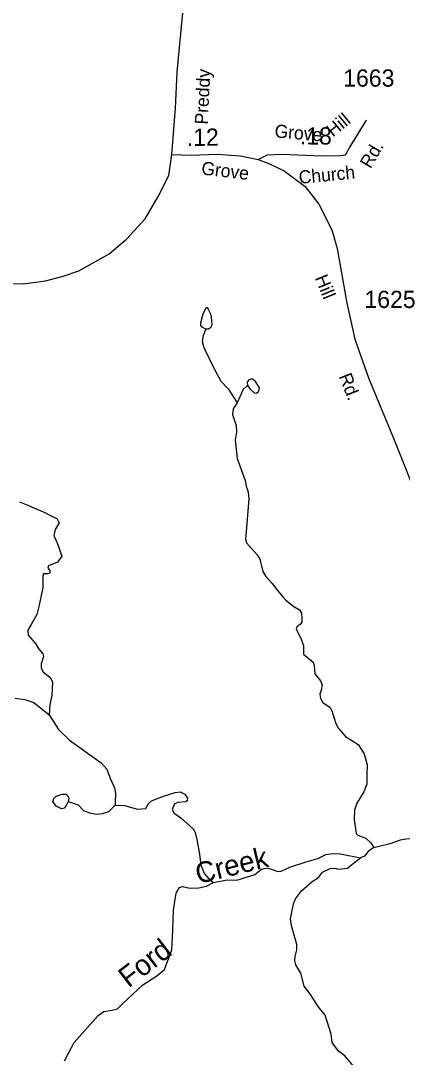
# Model space of a CAD drawing. Extents: x 2056842 to 2160602, y 826753 to 1016856.
# Drawn here: x 2135919 to 2138687, y 873341 to 880850 of the extents above; entities that cross this region are included whole.
import ezdxf

# ---------------------------------------------------------------- set-up
doc = ezdxf.new("R2010")
doc.units = 0
for name, color, linetype in [('Exist Hydrographic Creek Single Shore', 7, 'Continuous'), ('Exist Hydrographic Creek Single Shore Label', 7, 'Continuous'), ('Exist Hydrographic Misc Water Feature', 7, 'Continuous'), ('Exist Road Secondary Mileage Hundredths English Label', 7, 'Continuous'), ('Exist Road Secondary Type 20 Attributed', 7, 'Continuous'), ('Exist Road Secondary Type 41 Attributed', 7, 'Continuous'), ('Exist Road Secondary Type 51 Attributed', 7, 'Continuous'), ('Exist Road Secondary Type 51 Label', 7, 'Continuous'), ('Exist Road Secondary Type 51 Number Label', 7, 'Continuous')]:
    doc.layers.add(name, color=color, linetype=linetype)

msp = doc.modelspace()

# ---------------------------------------------------------------- linework, layer by layer
at = {"layer": 'Exist Hydrographic Creek Single Shore'}
for points in [[(2137487.9, 878081.8), (2137460, 878037.6), (2137454.3, 877997.6), (2137482.1, 877918.2), (2137483.3, 877868), (2137474.5, 877811.4), (2137490, 877677.9), (2137547.4, 877519.9), (2137554.9, 877478.5), (2137562.4, 877458.4), (2137570, 877433.3), (2137573.7, 877384.3), (2137567.5, 877300.1), (2137559.9, 877204.3), (2137548.4, 877094.2), (2137556.4, 877068.3), (2137635, 876980.7), (2137652.8, 876948.7), (2137675.4, 876860.8), (2137697.3, 876822.9), (2137742, 876773.1), (2137780.9, 876721.6), (2137819.9, 876675.1), (2137842.1, 876651.6), (2137900.2, 876607.3), (2137941.7, 876580.9), (2137955.5, 876557), (2137959.2, 876518.1)], [(2136186.7, 877060.3), (2136217.2, 876970.3), (2136185.4, 876928.2), (2136119.4, 876900), (2136115.7, 876883.9), (2136129.7, 876868), (2136129.7, 876848), (2136113.7, 876843.9), (2136084.5, 876843), (2136078.2, 876825.4), (2136078.2, 876743.8), (2136051.9, 876616.9), (2136036.8, 876547.8), (2135995.4, 876476.1), (2135971.5, 876435.9), (2135972.8, 876399), (2136024.2, 876339.9), (2136051.9, 876293.5), (2136079.5, 876263.3), (2136083.3, 876244.5), (2136068.2, 876191.7), (2136066.9, 876159), (2136082, 876132.6), (2136133.5, 876091.2), (2136148.6, 876059.8), (2136143.5, 875961.5), (2136131, 875897.4), (2136126.2, 875820.2)], [(2137959.2, 876518.1), (2137958, 876493), (2137945.4, 876476.6), (2137924.1, 876461.6), (2137916.5, 876445.2), (2137954.2, 876368.6), (2137970.5, 876322.1), (2137969.8, 876280.2), (2137969.8, 876260.2), (2138040.1, 876202.5), (2138048.1, 876178.6), (2138052.4, 876118.7), (2138094.9, 876067), (2138104.9, 876038.2), (2138097.4, 876000.5), (2138089.8, 875971.6), (2138094.9, 875942.7), (2138111.3, 875910.9), (2138163.9, 875873.6), (2138175.2, 875849.7), (2138204.1, 875758), (2138225.4, 875721.5), (2138274.4, 875665), (2138366.1, 875607.2), (2138411.3, 875539.4), (2138431.4, 875459.5), (2138428.9, 875394.1), (2138430.1, 875318.7), (2138408.2, 875264.3), (2138356.5, 875182.2), (2138340.9, 875130.1), (2138339.1, 875062.1), (2138351.4, 874962.2), (2138363.7, 874950.2), (2138423.6, 874928.4), (2138459, 874893.3), (2138481.6, 874859.4)], [(2135877.7, 875941.1), (2135949.6, 875931.4), (2136013.8, 875911.7), (2136126.2, 875820.2)], [(2136126.2, 875820.2), (2136192.6, 875714.5), (2136272.9, 875637.6), (2136501.4, 875474.3), (2136544.1, 875427.8), (2136565.4, 875367.5), (2136599.3, 875292.1), (2136605.6, 875251.9), (2136602.9, 875186.4), (2136602.9, 875166.4)], [(2136602.9, 875166.4), (2136670.8, 875164.8), (2136765.1, 875139.1), (2136826.8, 875143.4), (2136846.9, 875179.5), (2136866.6, 875199.5), (2136910.8, 875215.5), (2136954.6, 875231.9), (2137040.3, 875258.4), (2137076.4, 875262.5), (2137110.4, 875246.7), (2137128.7, 875218.8), (2137126.6, 875198.8), (2137114.7, 875190.7), (2137059, 875186.5), (2137035, 875176.3), (2137016.9, 875136.3), (2137031.1, 875108.4), (2137081.1, 875074.5), (2137169.7, 874995), (2137184.5, 874969), (2137197, 874917.4), (2137216.4, 874813.2), (2137226.7, 874733.2), (2137252.9, 874669.3), (2137283.1, 874633.5), (2137317.6, 874605.9)], [(2138481.6, 874859.4), (2138519.3, 874869.4), (2138598.4, 874889.5), (2138673.7, 874914.7), (2138713.9, 874922.2), (2138781.7, 874927.2), (2138838.2, 874915.9), (2138885.9, 874895.8), (2138938.7, 874865.7), (2138978.8, 874861.9), (2139011.5, 874868.2), (2139124.5, 874919.7), (2139176, 874934.8), (2139199.8, 874948.6), (2139221.2, 874949.9), (2139235, 874937.3), (2139266.4, 874892.1), (2139285.2, 874866.9), (2139527.6, 874828), (2139552.7, 874835.5), (2139586.6, 874885.8), (2139609.2, 874897.1)], [(2137317.6, 874605.9), (2137416.8, 874626), (2137487.1, 874624.7), (2137617.7, 874663.6), (2137666.7, 874702.6), (2137694.3, 874710.1), (2137724.7, 874707.2), (2137784.6, 874685.6), (2137808.6, 874687.8), (2137871.3, 874718.9), (2137990.6, 874756.6), (2138074.8, 874781.5), (2138132, 874809), (2138186, 874817.4), (2138236.1, 874813.4), (2138383.7, 874786.5)], [(2138481.6, 874859.4), (2138438.9, 874830.5), (2138412.5, 874796.6), (2138383.7, 874786.5)], [(2138350.8, 873256.5), (2138270.6, 873350.1), (2138224.5, 873385.9), (2138178.1, 873447.7), (2138171.8, 873507.6), (2138127.3, 873645.4), (2138077, 873709.2), (2138020.7, 873794.9), (2137976.4, 873854.8), (2137950.1, 873950.5), (2137913.6, 874010.4), (2137907.7, 874038.4), (2137909.3, 874070.4), (2137921.4, 874118.5), (2137921.2, 874158.5), (2137882.7, 874292.3), (2137876.3, 874344.2), (2137897.8, 874452.3), (2137911.6, 874488.3), (2137955.5, 874546.5), (2138033.2, 874614.8), (2138078.9, 874643), (2138108.8, 874681.1), (2138164.6, 874709.4), (2138196.6, 874709.5), (2138224.7, 874703.7), (2138288.7, 874709.9), (2138307.1, 874726.2), (2138342.4, 874754.1), (2138383.7, 874786.5)], [(2136235.2, 873315.3), (2136265.3, 873369.3), (2136306.5, 873447.2), (2136480.1, 873643.5), (2136521.5, 873672.4), (2136583, 873682.4), (2136620.7, 873692.5), (2136659.6, 873730.2), (2136804, 873864.6), (2136907, 873931.2), (2136962.2, 873977.7), (2137015, 874118.4), (2137022.5, 874264.1), (2137026.3, 874409.9), (2137046.4, 874529.2), (2137071.5, 874570.7), (2137091.6, 874578.2), (2137145.6, 874565.7), (2137212.1, 874568.2), (2137267.4, 874579.5), (2137317.6, 874605.9)]]:
    msp.add_lwpolyline(points, dxfattribs=at)
at = {"layer": 'Exist Hydrographic Misc Water Feature'}
for points in [[(2137261.1, 878616), (2137234.7, 878628.6), (2137224.7, 878642.4), (2137225.9, 878661.3), (2137243.5, 878726.6), (2137263.6, 878771.8), (2137272.4, 878773.1), (2137278.7, 878759.3), (2137295, 878726.6), (2137300, 878704), (2137305, 878646.2), (2137298.8, 878627.3), (2137281.2, 878614.8), (2137261.1, 878616)], [(2137261.1, 878616), (2137242.2, 878568.3), (2137236, 878529.3), (2137247.3, 878482.9), (2137316.3, 878338.4), (2137370.3, 878237.6), (2137423.5, 878183.4), (2137487.9, 878081.8)], [(2137565, 878206.2), (2137583.8, 878181.3), (2137611.4, 878153.7), (2137629, 878152.4), (2137646.6, 878165), (2137650.3, 878191.4), (2137621.5, 878236.6), (2137596.3, 878255.4), (2137573.7, 878249.2), (2137562.4, 878230.3), (2137565, 878206.2)], [(2137565, 878206.2), (2137531.6, 878177.9), (2137487.9, 878081.8)], [(2135909.4, 877365), (2135971.5, 877340.5), (2136019.6, 877319.4), (2136093.3, 877287), (2136126, 877270.7), (2136182, 877242.2), (2136198.2, 877212.3), (2136168.4, 877164.1), (2136158.4, 877120.1), (2136186.7, 877060.3)], [(2136262.8, 875194.1), (2136249, 875163.9), (2136233.9, 875146.4), (2136213.9, 875141.3), (2136174.9, 875160.2), (2136152.3, 875194.1), (2136158.6, 875215.5), (2136174.9, 875233.1), (2136218.9, 875246.9), (2136247.8, 875246.9), (2136260.3, 875235.6), (2136266.6, 875214.2), (2136262.8, 875194.1)], [(2136262.8, 875194.1), (2136334.9, 875169.3), (2136375.1, 875129.4), (2136425.1, 875109.7), (2136473.3, 875101.9), (2136513.1, 875106), (2136557.2, 875122.2), (2136602.9, 875166.4)]]:
    msp.add_lwpolyline(points, dxfattribs=at)
at = {"layer": 'Exist Road Secondary Type 20 Attributed'}
msp.add_lwpolyline([(2137014, 879881.6), (2137041.7, 880215.4), (2137053.1, 880477.8), (2137093.9, 880906.6), (2137109.1, 880999.7), (2137169.9, 881267.8), (2137208.9, 881439.9), (2137218.4, 881550.2), (2137248.8, 881991.4), (2137283.9, 882418.2), (2137285.8, 882469.6), (2137245.9, 882602.7)], dxfattribs=at)
at = {"layer": 'Exist Road Secondary Type 41 Attributed'}
msp.add_lwpolyline([(2137642.1, 879845.3), (2137708.6, 879878.8), (2137809.3, 879882.6), (2138105.8, 879871.2), (2138242, 879872.4), (2138276.1, 879878.4), (2138303.2, 879929.6), (2138427.5, 880128.2)], dxfattribs=at)
at = {"layer": 'Exist Road Secondary Type 51 Attributed'}
for points in [[(2132819.9, 877852.3), (2133038.4, 877880.8), (2133213.2, 877934), (2133393.7, 878015.8), (2133595.1, 878137.5), (2133860.2, 878368.5), (2134109.1, 878606.2), (2134289.7, 878764), (2134493.9, 878871.5), (2134685.8, 878947.5), (2134929.1, 878998.9), (2135162.8, 879004.6), (2135316.7, 878983.7), (2135735.7, 878946.6), (2135937.1, 878942.8), (2136098.6, 878965.6), (2136227.8, 878999.8), (2136340, 879037.9), (2136559.4, 879160.5), (2136686.7, 879267), (2136821.6, 879415.3), (2136914.8, 879576.9), (2136992.7, 879729), (2137014, 879881.6)], [(2137014, 879881.6), (2137154.7, 879875), (2137344.7, 879882.6), (2137513.8, 879871.2), (2137642.1, 879845.3)], [(2137642.1, 879845.3), (2137724.4, 879812.2), (2137829.7, 879763), (2137981.3, 879647.8), (2138082, 879520.4), (2138177, 879335.9), (2138215, 879199), (2138284.4, 878802.6), (2138343.3, 878542), (2138443.1, 878261.6), (2138627.4, 877814.7), (2138818.3, 877336.5)]]:
    msp.add_lwpolyline(points, dxfattribs=at)

# ---------------------------------------------------------------- texts
at = {"layer": 'Exist Hydrographic Creek Single Shore Label'}
for s, rotation, p in [('Creek', 13.74928, (2137206.4, 874594.9)), ('Ford', 37.7853, (2136701.5, 873838.1))]:
    msp.add_text(s, height=150, rotation=rotation, dxfattribs=at).set_placement(p)
at = {"layer": 'Exist Road Secondary Mileage Hundredths English Label'}
for s, rotation, p in [('.12', 0.5897, (2137123.9, 879942.1)), ('.18', 359.72677, (2137943.3, 879953.4))]:
    msp.add_text(s, height=125, rotation=rotation, dxfattribs=at).set_placement(p)
at = {"layer": 'Exist Road Secondary Type 51 Label'}
for s, rotation, p in [('Preddy', 87.25236, (2137275.8, 880096.2)), ('Hill', 39.23824, (2138183.8, 880002.6)), ('Grove', 354.98278, (2137757.4, 880005.2)), ('Rd.', 59.67337, (2138456, 879772.9)), ('Grove', 353.16169, (2137225.5, 879736.8)), ('Church', 5.47069, (2137940.3, 879667.6)), ('Hill', 291.90866, (2138051.6, 878987.3)), ('Rd.', 291.38069, (2138225.3, 878274.4))]:
    msp.add_text(s, height=95, rotation=rotation, dxfattribs=at).set_placement(p)
at = {"layer": 'Exist Road Secondary Type 51 Number Label'}
for s, p in [('1663', (2138258.1, 880372)), ('1625', (2138412.2, 878768.5))]:
    msp.add_text(s, height=125, dxfattribs=at).set_placement(p)

doc.saveas('drawing.dxf')
